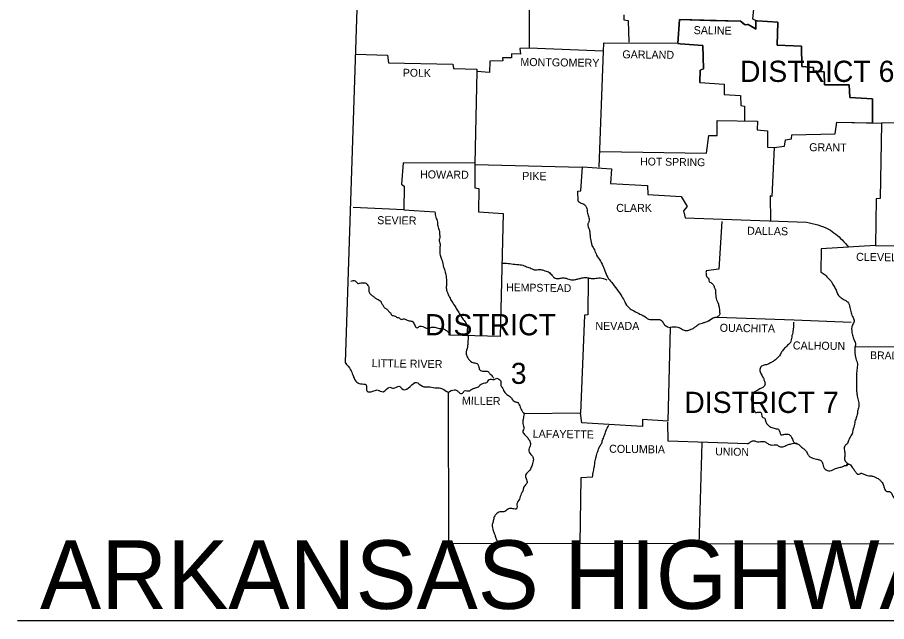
# Model space of a CAD drawing. Extents: x -31696 to 27919, y -8775 to 11152.
# Drawn here: x 9157 to 13726, y 4654 to 7830 of the extents above; entities that cross this region are included whole.
import ezdxf

# ---------------------------------------------------------------- set-up
doc = ezdxf.new("R2010")
doc.units = 0
for name, color, linetype in [('Level 1', 7, 'Continuous'), ('Level 2', 7, 'Continuous'), ('Level 3', 7, 'Continuous'), ('Level 48', 7, 'Continuous')]:
    doc.layers.add(name, color=color, linetype=linetype)

msp = doc.modelspace()

# ---------------------------------------------------------------- linework, layer by layer
at = {"layer": 'Level 1'}
msp.add_line((9156.5, 4659.5), (17226.8, 4659.5), dxfattribs=at)
for points in [[(10765.1, 10295.4), (10967.6, 8669.3), (10879.5, 6014.8)], [(11848.2, 8239.7), (11846.2, 7667.4), (11797.3, 7666.4), (11801.2, 7637), (11754.2, 7638), (11753.3, 7616.5), (11707.3, 7616.5), (11708.3, 7600.8), (11639.8, 7598.9), (11638.8, 7539.2), (11572.3, 7545.1), (11561.5, 7063.7), (11184.8, 7064.7), (11176, 6953.1), (11189.7, 6943.3), (11188.7, 6818.1), (10921.6, 6829.8)], [(13347.1, 7958.9), (13276.6, 7966.8), (13279.6, 7940.3), (13151.4, 7935.4), (13147.5, 7897.3), (13027.1, 7890.4), (13020.3, 7822), (13037.9, 7813.1), (13037.9, 7768.1)], [(12957.7, 7809.2), (12637.7, 7819), (12628.9, 7692.8), (12237.6, 7694.8), (12235.6, 7652.7)], [(12345.2, 7843.5), (12344.2, 7817.1), (12366.7, 7813.1), (12370.6, 7699.6)], [(12640.7, 7690.8), (12759.1, 7682), (12763, 7558.8), (12746.3, 7552.9), (12744.4, 7487.3), (12872.6, 7478.5), (12872.6, 7424.7), (12957.7, 7419.8), (12958.7, 7366), (12979.2, 7363.1), (12978.2, 7290.7)], [(10933.4, 7637), (11102.6, 7631.2), (11106.5, 7590.1), (11445.1, 7583.2), (11449, 7561.7), (11572.3, 7557.8), (11571.3, 7539.2)], [(12235.6, 7652.7), (11846.2, 7667.4)], [(12235.6, 7652.7), (12213.1, 7043.1)], [(14818.6, 7387.5), (14448.8, 7397.3), (14446.8, 7277), (13698.3, 7274)], [(12220, 7124.3), (12779.6, 7116.5), (12790.4, 7209.5), (12834.4, 7209.5), (12835.4, 7287.7), (13046.7, 7284.8), (13044.8, 7237.8), (13099.5, 7233.9), (13099.5, 7147.8), (13134.8, 7144.9)], [(13134.8, 7144.9), (13189.6, 7152.7), (13193.5, 7186), (13225.8, 7191.9), (13227.7, 7211.4), (13455.7, 7218.3), (13464.5, 7278), (13698.3, 7274)], [(13698.3, 7272.1), (13692.5, 6876.8), (13670, 6875.8), (13667, 6630.3)], [(13134.8, 7144.9), (13123, 6888.6), (13114.2, 6891.5), (13115.2, 6758.4)], [(11561.5, 7063.7), (11561.5, 6933.6), (11583, 6929.6), (11581.1, 6808.3), (11710.2, 6798.5), (11694.6, 6151.8), (11428.4, 6158.7)], [(11563.5, 7056.8), (12123.1, 7042.2)], [(12104.5, 6863.1), (12102.6, 6916.9), (12118.2, 6917.9), (12128, 7044.1), (12278.7, 7034.3), (12274.8, 6957), (12469.5, 6946.3), (12470.4, 6899.3), (12646.5, 6888.6), (12676.9, 6835.7), (12658.3, 6812.2), (12667.1, 6776), (13305, 6752.6)], [(11188.7, 6818.1), (11351.1, 6808.3)], [(12858.9, 6757.4), (12844.2, 6506), (12776.7, 6498.2)], [(13667, 6630.3), (13524.2, 6621.4)], [(13667, 6630.3), (14015.3, 6628.3)], [(13526.1, 6621.4), (13381.3, 6612.6), (13380.4, 6490.3)], [(12156.4, 6461), (12154.4, 6266.3), (12136.8, 6264.3), (12117.2, 5748.7)], [(12834.4, 6254.5), (13239.5, 6239.9), (13539.8, 6228.1)], [(12587.8, 6199.8), (12575.1, 5706.6), (12443, 5715.4), (12442.1, 5679.2), (12265.9, 5690)], [(13559.4, 6098), (14001.6, 6099)], [(11420.6, 5857.3), (11422.6, 5065.8), (15008.4, 5059.9)], [(12265.9, 5690), (12124.1, 5697.8), (12117.2, 5748.7), (11820.8, 5745.8)], [(12994.9, 5587.3), (12577.1, 5602.9), (12575.1, 5701.7)], [(12755.1, 5594.1), (12739.5, 5057)], [(12179.8, 5413.1), (12119.2, 5409.2), (12112.3, 5064.8)]]:
    msp.add_lwpolyline(points, dxfattribs=at)
for points in [[(13031.1, 7773), (13012.5, 7782.8), (12997.8, 7791.6), (12982.1, 7790.6), (12969.4, 7798.5), (12957.7, 7809.2)], [(12104.5, 6863.1), (12120.2, 6853.3), (12138.8, 6844.5), (12148.5, 6829.8), (12152.5, 6807.3), (12159.3, 6782.9), (12161.3, 6757.4), (12155.4, 6743.7), (12163.2, 6712.4), (12166.1, 6690.9), (12169.1, 6665.5), (12176.9, 6631.2), (12189.6, 6607.7), (12201.4, 6579.4), (12220.9, 6549), (12237.6, 6515.8), (12245.4, 6498.2), (12260.1, 6462), (12278.7, 6437.5), (12308, 6400.3), (12334.4, 6362.2), (12349.1, 6333.8), (12371.6, 6302.5), (12397.1, 6286.8), (12429.3, 6270.2), (12449.9, 6260.4), (12473.4, 6243.8), (12503.7, 6241.8), (12526.2, 6241.8), (12546.7, 6233), (12556.5, 6215.4), (12574.1, 6203.7), (12587.8, 6199.8)], [(11351.1, 6808.3), (11356, 6779), (11364.8, 6753.5), (11365.8, 6734), (11374.6, 6704.6), (11374.6, 6693.8), (11377.6, 6672.3), (11373.6, 6660.6), (11378.5, 6637.1), (11377.6, 6619.5), (11377.6, 6604.8), (11378.5, 6580.4), (11386.4, 6558.8), (11394.2, 6526.5), (11399.1, 6509.9), (11406.9, 6484.5), (11411.8, 6453.2), (11412.8, 6429.7), (11410.8, 6408.2), (11416.7, 6383.7), (11427.5, 6359.2), (11441.1, 6335.8), (11457.8, 6309.3), (11469.5, 6288.8), (11484.2, 6266.3), (11495.9, 6247.7), (11513.6, 6224.2), (11521.4, 6204.6), (11521.4, 6177.2), (11525.3, 6151.8), (11524.3, 6123.4), (11522.4, 6098), (11515.5, 6062.8), (11520.4, 6046.1), (11539, 6021.7), (11550.7, 6014.8), (11571.3, 6010.9), (11581.1, 5997.2), (11586.9, 5976.7), (11607.5, 5969.8), (11630, 5967.9), (11640.7, 5956.1), (11655.4, 5940.5), (11660.3, 5932.6)], [(13305, 6752.6), (13420.5, 6716.4), (13491.9, 6659.6), (13525.9, 6621.5)], [(11708.3, 6538.3), (11745.4, 6535.3), (11779.7, 6531.4), (11806.1, 6528.5), (11833.5, 6518.7), (11858, 6509.9), (11873.6, 6503.1), (11900, 6505), (11922.5, 6500.1), (11948, 6491.3), (11966.6, 6474.7), (11978.3, 6462), (12000.8, 6457.1), (12019.4, 6460), (12041.9, 6458.1), (12067.3, 6450.2), (12087.9, 6451.2), (12104.5, 6455.1), (12124.1, 6460), (12148.5, 6462), (12167.1, 6458.1), (12191.6, 6457.1), (12220, 6460), (12255.2, 6450.2)], [(12776.7, 6498.2), (12776.7, 6479.6), (12783.5, 6462), (12790.4, 6454.1), (12793.3, 6441.4), (12802.1, 6435.5), (12814.8, 6423.8), (12821.7, 6407.2), (12826.6, 6396.4), (12826.6, 6382.7), (12827.6, 6369), (12829.5, 6352.4), (12841.2, 6323), (12844.2, 6311.3), (12846.1, 6301.5), (12847.1, 6284.9), (12847.1, 6265.3), (12834.4, 6254.5)], [(13380.4, 6490.3), (13402.9, 6475.7), (13421.4, 6456.1), (13435.1, 6441.4), (13443.9, 6424.8), (13455.7, 6405.2), (13472.3, 6368), (13487, 6355.3), (13507.5, 6342.6), (13520.3, 6333.8), (13533, 6305.4), (13538.9, 6277), (13549.6, 6251.6), (13554.5, 6232), (13545.7, 6212.5), (13543.7, 6173.3), (13549.6, 6146.9), (13557.4, 6127.3), (13562.3, 6104.8), (13559.4, 6098)], [(10909.9, 6443.4), (10931.4, 6444.4), (10946.1, 6431.6), (10954.9, 6432.6), (10970.5, 6434.6), (10985.2, 6433.6), (10996, 6424.8), (11004.8, 6409.1), (11003.8, 6394.5), (11004.8, 6388.6), (11011.6, 6375.9), (11023.4, 6366.1), (11036.1, 6356.3), (11047.8, 6348.5), (11067.4, 6335.8), (11069.4, 6331.8), (11077.2, 6316.2), (11087, 6303.5), (11098.7, 6295.6), (11111.4, 6281.9), (11117.3, 6276.1), (11127.1, 6262.4), (11137.8, 6261.4), (11152.5, 6252.6), (11163.3, 6249.7), (11175, 6241.8), (11186.8, 6245.7), (11201.4, 6239.9), (11221, 6234), (11231.8, 6232), (11244.5, 6213.4), (11257.2, 6197.8), (11272.9, 6206.6), (11302.2, 6197.8), (11320.8, 6196.8), (11337.4, 6201.7), (11350.2, 6200.7), (11373.6, 6194.9), (11388.3, 6194.9), (11404, 6189), (11418.6, 6177.2), (11428.4, 6164.5), (11428.4, 6158.7)], [(12815.8, 6250.6), (12790.4, 6234), (12770.8, 6226.2), (12756.1, 6221.3), (12742.4, 6217.4), (12724.8, 6205.6), (12711.1, 6195.8), (12692.5, 6187), (12674.9, 6181.2), (12653.4, 6188), (12641.7, 6194.9), (12628.9, 6199.8), (12587.8, 6199.8)], [(12790.4, 6234), (12815.8, 6250.6), (12834.4, 6254.5)], [(13235.5, 6228.1), (13233.6, 6179.2), (13226.7, 6148.9), (13219.9, 6121.5), (13205.2, 6105.8), (13189.6, 6090.2), (13174.9, 6072.6), (13162.2, 6051), (13149.4, 6037.3), (13132.8, 6023.6), (13116.2, 6013.9), (13097.6, 6005), (13077, 6000.2), (13062.4, 5989.4), (13061.4, 5965.9), (13078, 5932.6), (13083.9, 5917), (13085.9, 5898.4), (13079, 5887.6), (13063.3, 5878.8), (13044.8, 5868.1), (13028.1, 5858.3), (13016.4, 5841.7), (13014.4, 5819.2), (13022.3, 5792.7), (13025.2, 5777.1), (13037.9, 5752.6), (13047.7, 5753.6), (13065.3, 5752.6), (13067.3, 5747.7), (13068.2, 5742.8), (13072.2, 5730.1), (13086.8, 5719.4), (13088.8, 5709.6), (13097.6, 5691), (13112.3, 5678.3), (13123, 5674.3), (13145.5, 5667.5), (13157.3, 5664.6), (13170, 5636.2), (13185.6, 5637.2), (13197.4, 5639.1), (13217, 5634.2), (13225.8, 5622.5), (13234.6, 5602.9), (13246.3, 5589.2), (13254.1, 5589.2)], [(13559.4, 6098), (13563.3, 6037.3), (13572.1, 6008), (13569.2, 5976.7), (13568.2, 5946.3), (13568.2, 5918.9), (13568.2, 5892.5), (13568.2, 5865.1), (13570.2, 5845.6), (13577, 5817.2), (13579.9, 5790.8), (13574.1, 5765.3), (13571.1, 5741.9), (13563.3, 5718.4), (13556.5, 5692), (13548.6, 5657.7), (13541.8, 5635.2), (13528.1, 5611.7), (13519.3, 5590.2), (13505.6, 5576.5), (13503.6, 5553), (13506.6, 5531.5), (13504.6, 5511.9), (13511.5, 5493.3), (13529.1, 5480.6)], [(10879.5, 6014.8), (10907.9, 5977.7), (10919.7, 5951.2), (10936.3, 5917), (10960.8, 5903.3), (10989.1, 5898.4), (10995, 5865.1), (11024.3, 5864.2), (11047.8, 5871), (11080.1, 5862.2), (11114.4, 5885.7), (11133.9, 5879.8), (11162.3, 5891.6), (11183.8, 5873.9), (11221, 5889.6), (11254.3, 5911.1), (11285.6, 5890.6), (11315.9, 5887.6), (11352.1, 5882.7), (11380.5, 5880.8), (11405.9, 5868.1), (11424.5, 5855.4), (11420.6, 5857.3)], [(11420.6, 5857.3), (11454.8, 5872), (11469.5, 5867.1), (11482.2, 5854.4), (11496.9, 5854.4), (11504.7, 5866.1), (11519.4, 5867.1), (11531.2, 5866.1), (11543.9, 5873.9), (11554.6, 5878.8), (11569.3, 5883.7), (11580.1, 5887.6), (11589.9, 5898.4), (11607.5, 5907.2), (11628, 5914.1), (11633.9, 5923.8), (11643.7, 5927.8), (11663.2, 5926.8), (11676, 5932.6), (11686.7, 5927.8), (11696.5, 5920.9), (11698.5, 5895.5), (11706.3, 5881.8), (11718, 5857.3), (11734.7, 5844.6), (11750.3, 5831.9), (11756.2, 5824), (11772.8, 5809.4), (11787.5, 5804.5), (11794.4, 5793.7), (11805.1, 5768.3), (11820.8, 5745.8)], [(11820.8, 5745.8), (11814.9, 5717.4), (11813.9, 5694.9), (11818.8, 5668.5), (11813.9, 5655.8), (11821.7, 5637.2), (11836.4, 5622.5), (11847.2, 5606.8), (11854, 5584.3), (11845.2, 5558.9), (11855, 5532.5), (11863.8, 5522.7), (11868.7, 5507), (11861.9, 5476.7), (11853.1, 5454.2), (11833.5, 5431.7), (11827.6, 5420.9), (11830.6, 5406.3), (11835.4, 5382.8), (11830.6, 5375.9), (11817.8, 5359.3), (11813.9, 5340.7), (11805.1, 5325.1), (11795.3, 5296.7), (11782.6, 5273.2), (11780.7, 5246.8), (11761.1, 5246.8), (11738.6, 5246.8), (11718, 5232.1), (11699.4, 5231.1), (11676.9, 5222.3), (11663.2, 5203.7), (11658.4, 5183.2), (11652.5, 5163.6), (11658.4, 5130.4), (11667.2, 5106.9), (11674, 5088.3), (11685.8, 5058)], [(12179.8, 5413.1), (12184.7, 5444.4), (12189.6, 5468.9), (12192.6, 5492.4), (12198.4, 5518.8), (12207.2, 5547.2), (12215.1, 5570.6), (12225.8, 5587.3), (12232.7, 5606.8), (12241.5, 5630.3), (12250.3, 5654.8), (12265.9, 5686.1)], [(12994.9, 5587.3), (13010.5, 5598), (13025.2, 5603.9), (13039.9, 5601), (13055.5, 5599), (13069.2, 5601), (13086.8, 5598), (13101.5, 5589.2), (13118.1, 5582.4), (13134.8, 5582.4), (13149.4, 5582.4), (13162.2, 5573.6), (13185.6, 5574.5), (13205.2, 5582.4), (13224.8, 5588.2), (13251.2, 5591.2), (13274.7, 5574.5), (13291.3, 5560.9), (13305, 5545.2), (13314.8, 5527.6), (13325.6, 5517.8), (13343.2, 5511), (13356.9, 5508), (13373.5, 5503.1), (13382.3, 5499.2), (13390.1, 5480.6), (13402.9, 5455.2), (13427.3, 5446.4), (13457.6, 5458.1), (13482.1, 5465), (13499.7, 5470.8), (13510.5, 5474.8), (13520.3, 5475.7), (13517.3, 5477.7), (13529.1, 5480.6), (13539.8, 5472.8), (13546.7, 5462), (13558.4, 5446.4), (13569.2, 5432.7), (13579.9, 5427.8), (13590.7, 5433.7), (13605.4, 5428.8), (13618.1, 5423.9), (13632.8, 5420), (13645.5, 5419), (13662.1, 5415.1), (13674.9, 5408.2), (13686.6, 5401.4), (13698.3, 5388.7), (13710.1, 5369.1), (13714, 5353.4), (13727.7, 5337.8), (13740.4, 5337.8), (13759, 5312.3), (13765.8, 5302.6), (13780.5, 5284.9), (13791.3, 5284.9), (13811.8, 5281)]]:
    msp.add_spline(points, degree=3, dxfattribs=at)
at = {"layer": 'Level 48'}
msp.add_line((12759.1, 7682), (12763, 7558.8), dxfattribs=at)
for points in [[(12744.4, 7487.3), (12746.3, 7552.9), (12763, 7558.8), (12759.1, 7682), (12640.7, 7690.8), (12628.9, 7692.8), (12637.7, 7819), (12797.7, 7814.1), (12957.7, 7809.2), (12982.1, 7790.6), (12997.8, 7791.6), (13031.1, 7773), (13037.9, 7768.1), (13037.9, 7813.1), (13044.8, 7812.2), (13154.3, 7805.3), (13150.4, 7683), (13278.6, 7678.1), (13280.6, 7571.5), (13341.2, 7566.6), (13341.2, 7548), (13398, 7544.1), (13399.9, 7475.6), (13529.1, 7475.6), (13533, 7408.1), (13652.3, 7402.2), (13651.4, 7275)], [(13651.4, 7275), (13652.3, 7402.2), (13533, 7408.1), (13529.1, 7475.6), (13399.9, 7475.6), (13398, 7544.1), (13341.2, 7548), (13341.2, 7566.6), (13280.6, 7571.5), (13278.6, 7678.1), (13150.4, 7683), (13154.3, 7805.3), (13044.8, 7812.2), (13037.9, 7813.1), (13037.9, 7768.1), (13031.1, 7773), (12997.8, 7791.6), (12982.1, 7790.6), (12957.7, 7809.2), (12797.7, 7814.1), (12637.7, 7819), (12628.9, 7692.8), (12640.7, 7690.8), (12759.1, 7682)], [(12763, 7558.8), (12746.3, 7552.9), (12744.4, 7487.3)], [(12744.4, 7487.3), (12872.6, 7478.5), (12872.6, 7424.7), (12957.7, 7419.8), (12958.7, 7366), (12979.2, 7363.1), (12978.2, 7290.7)], [(12978.2, 7290.7), (12978.5, 7285.7), (13046.7, 7284.8), (13044.8, 7237.8), (13099.5, 7233.9), (13099.5, 7147.8), (13134.8, 7144.9), (13189.6, 7152.7), (13193.5, 7186), (13225.8, 7191.9), (13227.7, 7211.4), (13455.7, 7218.3), (13464.5, 7278), (13651.4, 7274.8), (13652.3, 7402.2)], [(12978.2, 7290.7), (12978.5, 7285.7), (13046.7, 7284.8), (13044.8, 7237.8), (13099.5, 7233.9), (13099.5, 7147.8), (13134.8, 7144.9), (13189.6, 7152.7), (13193.5, 7186), (13225.8, 7191.9), (13227.7, 7211.4), (13455.7, 7218.3), (13464.5, 7278), (13651.4, 7275)]]:
    msp.add_lwpolyline(points, dxfattribs=at)

# ---------------------------------------------------------------- texts
at = {"layer": 'Level 2'}
for s, height, rotation, p in [('SALINE', 42.07, 359.1491, (12711.1, 7741.7)), ('GARLAND', 42.07, 359.3658, (12336.4, 7614.5)), ('MONTGOMERY', 42.07, 359.2944, (11800.2, 7574.4)), ('POLK', 41.08, 359.2152, (11182.9, 7518.6)), ('GRANT', 42.07, 359.4032, (13318.7, 7126.3)), ('HOT SPRING', 41.09, 359.2216, (12430.3, 7051.9)), ('HOWARD', 42.07, 359.5145, (11272.9, 6983.5)), ('PIKE', 42.06, 359.0452, (11810, 6975.6)), ('SEVIER', 42.07, 359.4271, (11047.8, 6742.8)), ('DALLAS', 42.06, 359.2462, (12991.9, 6687)), ('CLEVELAND', 42.07, 359.3377, (13565.3, 6550)), ('HEMPSTEAD', 41.08, 359.1885, (11725.9, 6390.5)), ('OUACHITA', 42.07, 359.2043, (12848.1, 6177.2)), ('CALHOUN', 42.07, 359.3634, (13232.6, 6084.3)), ('LITTLE RIVER', 42.073, 359.1697, (11018.5, 5991.4)), ('BRADLEY', 41.08, 359.1449, (13638.7, 6033.4)), ('MILLER', 42.06, 359.1319, (11493, 5794.7)), ('LAFAYETTE', 42.06, 359.1839, (11864.8, 5620.5)), ('COLUMBIA', 42.06, 359.2125, (12266.9, 5541.3)), ('UNION', 41.09, 358.9584, (12824.6, 5527.6))]:
    msp.add_text(s, height=height, rotation=rotation, dxfattribs=at).set_placement(p)
for s, height, p in [('CLARK', 42.07, (12304.3, 6807.1)), ('NEVADA', 42.07, (12194.5, 6187)), ('ARKANSAS HIGHWAY DISTRICTS 1, 2 & 6', 360, (9275.5, 4720.5))]:
    msp.add_text(s, height=height, dxfattribs=at).set_placement(p)
at = {"layer": 'Level 3'}
for s, height, p in [('DISTRICT 6', 111.54, (12954.7, 7490.3)), ('DISTRICT', 111.54, (11299.6, 6158.4)), ('3', 110.6, (11750.6, 5903.1)), ('DISTRICT 7', 111.54, (12662, 5750.3))]:
    msp.add_text(s, height=height, dxfattribs=at).set_placement(p)

doc.saveas('drawing.dxf')
